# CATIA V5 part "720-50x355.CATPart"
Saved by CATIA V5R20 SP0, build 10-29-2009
Part number: 720-50x355
Definition: NONE
Nomenclature: 720-50x355
Source: Unknown
Description: 720-50x355
Bounding box of the stored display mesh (mm): x 0 to 355, y -25 to 25, z -25 to 25
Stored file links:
  C:\Users\Utente\Desktop\IO LAVORO\3D X SITO CF\X SITO\720\720-50x355.CATPart
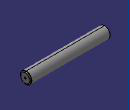
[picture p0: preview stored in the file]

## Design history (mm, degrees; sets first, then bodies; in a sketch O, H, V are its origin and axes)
Body1 "720-50x355" (main body)
  Solid1: solid without history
